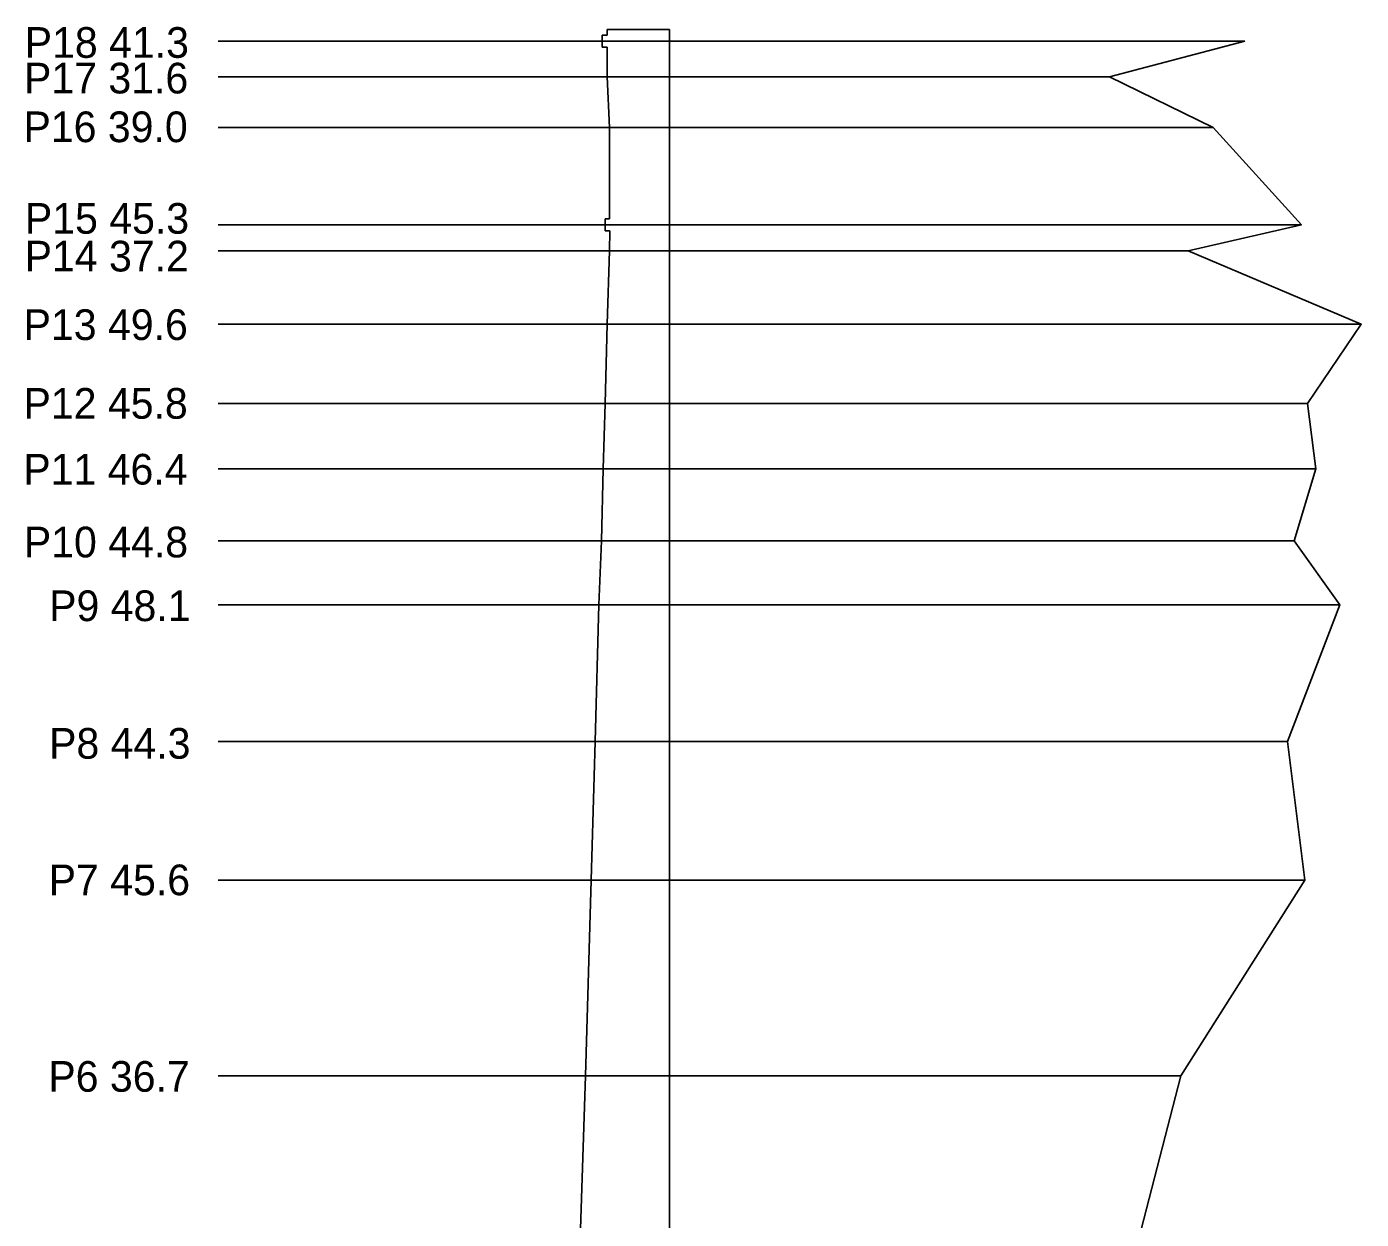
# Model space of a CAD drawing. Extents: x 138 to 6653, y -177 to 1520.
# Drawn here: x 172.66 to 182.23, y 99.52 to 108.07 of the extents above; entities that cross this region are included whole.
import ezdxf

# ---------------------------------------------------------------- set-up
doc = ezdxf.new("R2010")
doc.units = 0
doc.layers.add('Standart wykresów', color=7, linetype='Continuous')
doc.layers.add('Wykresy 4 maj 2008', color=7, linetype='Continuous')

msp = doc.modelspace()

# ---------------------------------------------------------------- linework, layer by layer
at = {"layer": 'Standart wykresów'}
for p, q in [((176.7826, 108.0091), (176.7826, 107.967)), ((176.82, 108.0091), (176.7826, 108.0091)), ((176.82, 108.0513), (176.82, 108.0091)), ((176.82, 108.0513), (177.2655, 108.0513)), ((177.2655, 87.9671), (177.2655, 108.0513)), ((177.2655, 107.967), (174.0284, 107.967)), ((176.7826, 107.967), (176.7826, 107.9248)), ((176.82, 107.9248), (176.7826, 107.9248)), ((176.82, 107.7111), (176.82, 107.9248)), ((177.2655, 107.7111), (174.0284, 107.7111)), ((176.8349, 107.3482), (176.82, 107.7111)), ((177.2655, 107.3482), (174.0284, 107.3482)), ((176.8349, 107.3482), (176.8349, 106.6943)), ((177.2655, 106.6503), (174.0284, 106.6503)), ((176.805, 106.6943), (176.805, 106.6503)), ((176.805, 106.6943), (176.8349, 106.6943)), ((176.805, 106.6503), (176.805, 106.6063)), ((176.839, 106.6063), (176.805, 106.6063)), ((176.8349, 106.4626), (176.839, 106.6063)), ((177.2655, 106.4626), (174.0284, 106.4626)), ((176.82, 105.9369), (176.8349, 106.4626)), ((177.2655, 105.9369), (174.0284, 105.9369)), ((176.805, 105.3689), (176.82, 105.9369)), ((177.2655, 105.3689), (174.0284, 105.3689)), ((176.7901, 104.9015), (176.805, 105.3689)), ((177.2655, 104.9015), (174.0284, 104.9015)), ((176.7776, 104.3842), (176.7901, 104.9015)), ((177.2655, 104.3842), (174.0284, 104.3842)), ((176.7602, 103.9253), (176.7776, 104.3842)), ((177.2655, 103.9253), (174.0284, 103.9253)), ((176.7328, 102.9446), (176.7602, 103.9253)), ((177.2655, 102.9446), (174.0284, 102.9446)), ((176.703, 101.9515), (176.7328, 102.9446)), ((177.2655, 101.9515), (174.0284, 101.9515)), ((176.6631, 100.5491), (176.703, 101.9515)), ((177.2655, 100.5491), (174.0284, 100.5491)), ((176.6183, 99.1583), (176.6631, 100.5491))]:
    msp.add_line(p, q, dxfattribs=at)
at = {"layer": 'Wykresy 4 maj 2008'}
for p, q in [((177.2655, 107.967), (181.3915, 107.967)), ((177.2655, 107.7111), (180.4205, 107.7111)), ((177.2655, 107.3482), (181.1655, 107.3482)), ((177.2655, 106.6503), (181.7985, 106.6503)), ((177.2655, 106.4626), (180.9865, 106.4626)), ((177.2655, 105.9369), (182.2275, 105.9369)), ((177.2655, 105.3689), (181.8415, 105.3689)), ((177.2655, 104.9015), (181.9025, 104.9015)), ((177.2655, 104.3842), (181.7455, 104.3842)), ((177.2655, 103.9253), (182.0725, 103.9253)), ((177.2655, 102.9446), (181.6985, 102.9446)), ((177.2655, 101.9515), (181.8225, 101.9515)), ((177.2655, 100.5491), (180.9335, 100.5491))]:
    msp.add_line(p, q, dxfattribs=at)
msp.add_lwpolyline([(181.3915, 107.967), (180.4205, 107.7111), (181.1655, 107.3482), (181.7985, 106.6503), (180.9865, 106.4626), (182.2275, 105.9369), (181.8415, 105.3689), (181.9025, 104.9015), (181.7455, 104.3842), (182.0725, 103.9253), (181.6985, 102.9446), (181.8225, 101.9515), (180.9335, 100.5491), (180.5755, 99.1583), (179.8265, 97.7992), (179.1555, 96.4412), (178.6715, 95.0738), (177.8275, 93.6983), (177.2655, 92.2527)], dxfattribs=at)

# ---------------------------------------------------------------- texts
for s, p in [('P18 41.3', (172.6417, 107.8476)), ('P17 31.6', (172.6366, 107.5923)), ('P16 39.0', (172.6328, 107.2429)), ('P15 45.3', (172.6429, 106.5864)), ('P14 37.2', (172.6412, 106.3157)), ('P13 49.6', (172.6336, 105.8243)), ('P12 45.8', (172.6331, 105.2599)), ('P11 46.4', (172.6318, 104.7877)), ('P10 44.8', (172.6355, 104.2655)), ('P9 48.1', (172.8169, 103.8086)), ('P8 44.3', (172.8165, 102.8219)), ('P7 45.6', (172.8134, 101.8429)), ('P6 36.7', (172.8112, 100.4339))]:
    msp.add_text(s, height=0.22, dxfattribs=at).set_placement(p)

doc.saveas('drawing.dxf')
